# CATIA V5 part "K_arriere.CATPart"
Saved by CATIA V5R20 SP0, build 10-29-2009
Part number: arriere
Bounding box of the stored display mesh (mm): x -100 to 100, y 75.582 to 866, z -5 to 72.258
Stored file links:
  G:\Khaled_CFAO_2011\SIL\SIL_GR2\ahabrial\ahabrial\Khaled\CAD_ThinkMOTION\K_arriere.CATPart
  G:\Données\Ecole\IFMA\2A\Thinkmotion2\Etape18\trotinette.CATProduct
  G:\Khaled_CFAO_2011\SIL\SIL_GR2\ahabrial\ahabrial\Khaled\CAD_ThinkMOTION\K_avant.CATPart
  G:\Khaled_CFAO_2011\SIL\SIL_GR2\ahabrial\ahabrial\Khaled\CAD_ThinkMOTION\K_skl_arriere.CATPart
  G:\Khaled_CFAO_2011\SIL\SIL_GR2\ahabrial\ahabrial\Khaled\CAD_ThinkMOTION\K_guidon.CATPart
  G:\Khaled_CFAO_2011\SIL\SIL_GR2\ahabrial\ahabrial\Khaled\CAD_ThinkMOTION\K_skl_frein.CATPart
  G:\Khaled_CFAO_2011\SIL\SIL_GR2\ahabrial\ahabrial\Khaled\CAD_ThinkMOTION\K_bati.CATPart
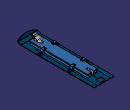
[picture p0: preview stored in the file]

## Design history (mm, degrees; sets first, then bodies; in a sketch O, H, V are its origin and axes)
Parameters
  `Longueur-arriere` = 740 mm
  Largeur_bande = 5 mm
  Profondeur_bande = 2 mm
  Longueur_arriere_trotinette = 590 mm
  Largeur_arriere_trotinette = 100 mm
  espace_frein = 50 mm
  epaisseur_arriere_trotinette = 30 mm
  `Diametre_trou_arriere trotinette` = 20 mm
  `epaisseur_supérieur_plateau_arriere_trotinette` = 10 mm
  Largeur_accroche_arriere = 25 mm
  Epaisseur_accroche_arriere = 10 mm
  Diametre_vis_accroche = 10 mm
  `Longueur_frein ` = 20 mm
External parameters (linked from other documents)
  External.epaisseur_planche_avant = 5 mm
  External.Largeur_planche_avant = 200 mm
  External.Longueur_arriere = 500 mm
  External.Hauteur_epaisseur_bati = 20 mm
  External.Largeur_epaisseur_bati = 10 mm
Set1
  Plane1 "Plan_avant_guidon": linked copy from another document
  Point1: linked copy from another document
  Line1 "Droite_arriere": linked copy from another document
  Line2 "Axe_frein_arriere": linked copy from another document
  Point2 "Point.4_frein": linked copy from another document
  Line3: linked copy from another document
  Line4 "Droite_frein": linked copy from another document
  Point3 "Point.3_arriere": linked copy from another document
  Plane2 "Plan_bati2": linked copy from another document
  Point4 "Point_construction": linked copy from another document
Body1 (main body)
  Sketch1 on Plane1, origin (0, 0, 0), H (1, 0, 0), V (0, -1, 0)
    line L1 (-100, -126) -> (100, -126)
    line L2 (100, -126) -> (100, -866)
    line L3 (100, -866) -> (-100, -866)
    line L4 (-100, -866) -> (-100, -126)
    reference projected point E1 (0, -200) from Point1
    reference projected point E2 (0, -200) from Point1
    length L4 = 740 {= `Longueur-arriere`}
    distance L1 E1 = 74 {= `Longueur-arriere` /10}
    distance E2 L4 = 100 {= External.Largeur_planche_avant /2}
    length L1 = 200 {= External.Largeur_planche_avant}
    horizontal: L1 H, L3 H
    vertical: L2 V, L4 V
  Pad1: profile Sketch1, direction (0, 0, -1), length 5 {= External.epaisseur_planche_avant}
  Sketch2 on end face of Pad1, origin (0, 0, -5), H (1, 0, 0), V (0, -1, 0)
    line L1 (-2.5, -220) -> (2.5, -220)
    line L2 (2.5, -220) -> (2.5, -890)
    line L3 (2.5, -890) -> (-2.5, -890)
    line L4 (-2.5, -890) -> (-2.5, -220)
    point P5 (64.1667, -220)
    line L5 (64.1667, -220) -> (69.1667, -220)
    line L6 (69.1667, -220) -> (69.1667, -890)
    line L7 (69.1667, -890) -> (64.1667, -890)
    line L8 (64.1667, -890) -> (64.1667, -220)
    point P6 (69.1667, -220)
    point P7 (69.1667, -890)
    point P8 (64.1667, -890)
    reference projected line E1 (0, -200) -> (0, -700) from Line1
    axis line L9 (66.6667, -313.0308) -> (66.6667, -613.0308)
    reference projected line E2 (0, -200) -> (0, -700) from Line1
    reference projected line E3 (0, -200) -> (0, -700) from edge of Line1
    point P13 (-64.1667, -220)
    point P14 (-64.1667, -890)
    line L10 (-64.1667, -890) -> (-64.1667, -220)
    reference projected line E4 (0, -200) -> (0, -700) from edge of Line1
    point P17 (-69.1667, -890)
    point P18 (-69.1667, -220)
    line L11 (-69.1667, -220) -> (-69.1667, -890)
    reference projected line E5 (0, -200) -> (0, -700) from edge of Line1
    point P21 (-69.1667, -220)
    point P22 (-64.1667, -220)
    line L12 (-64.1667, -220) -> (-69.1667, -220)
    reference projected line E6 (0, -200) -> (0, -700) from edge of Line1
    point P25 (-64.1667, -890)
    point P26 (-69.1667, -890)
    line L13 (-69.1667, -890) -> (-64.1667, -890)
    length L3 = 5 {= Largeur_bande}
    length L7 = 5 {= Largeur_bande}
    distance E1 L4 = 2.5 {= Largeur_bande /2}
    distance L9 E2 = 66.6667 {= External.Largeur_planche_avant /3}
    distance L9 L8 = 2.5 {= Largeur_bande /2}
    horizontal: L1 H, L3 H, L5 H, L7 H
    vertical: L2 V, L4 V, L6 V, L8 V, L9 V
    coincidence: P5 L1, P7 L3
    symmetry: P5 P13 E3, P8 P14 E3, L8 L10 E3, P7 P17 E4, P6 P18 E4, L6 L11 E4, P6 P21 E5, P5 P22 E5, L5 L12 E5, P8 P25 E6, P7 P26 E6, L7 L13 E6
  Pocket1: profile Sketch2, direction (0, 0, 1), length 2 {= Profondeur_bande}
  Plane3 "Plan_arriere_haut": type 2Lines, Element1 Line1, Element2 Line2
  Sketch3 on Plane3, origin (0, 0, 0), H (1, 0, 0), V (0, -1, 0)
    line L1 (-50, -160) -> (50, -160)
    line L2 (50, -160) -> (50, -750)
    line L3 (50, -750) -> (-50, -750)
    line L4 (-50, -750) -> (-50, -160)
    reference projected line E1 (0, -200) -> (0, -700) from Line1
    reference projected point E2 (0, -700) from Point2
    reference projected point E3 (0, -200) from Point3
    length L1 = 100 {= Largeur_arriere_trotinette}
    distance E1 L4 = 50 {= Largeur_arriere_trotinette /2}
    distance E2 L3 = 50 {= espace_frein}
    distance L1 E3 = 40 {= Longueur_arriere_trotinette -espace_frein -External.Longueur_arriere}
    horizontal: L1 H, L3 H
    vertical: L2 V, L4 V
  Pad2: profile Sketch3, direction (0, 0, 1), length 30 {= epaisseur_arriere_trotinette}
  Sketch4 on face of Pad2 from Sketch3.L3, origin (0, 750, 0), H (-1, 0, 0), V (0, 0, 1)
    circle A1 centre (-25, 15) radius 10
    point P1 (-25, 15)
    reference projected line E1 (0, 350) -> (0, 0) from Line3
    reference projected line E2 (20, 0) -> (-20, 0) from Line2
    circle A2 centre (25, 15) radius 10
    radius A1 = 10 {= `Diametre_trou_arriere trotinette` /2}
    distance E1 P1 = 25 {= Largeur_arriere_trotinette  /4}
    distance P1 E2 = 15 {= epaisseur_arriere_trotinette /2}
    symmetry: A1 A2 V
  Pocket2: profile Sketch4, direction (0, 1, 0), through (limit type 6)
  Sketch5 on face of Pad2 from Sketch3.L3, origin (0, 750, 0), H (-1, 0, 0), V (0, 0, 1)
    point P1 (25, 14.9997)
    reference projected line E1 (0, 350) -> (0, 0) from Line3
    reference projected line E2 (100, -0.0003) -> (-100, -0.0003) from edge [face of Pad1 | face of Pad1]
    line L1 (50, 19.9997) -> (37.3603, 19.9997)
    point P2 (50, 19.9997)
    point P3 (37.3603, 19.9997)
    line L2 (30, 0) -> (30, 2.6394)
    point P4 (30, 0)
    point P5 (30, 2.6394)
    reference projected line E3 (50, 0) -> (50, 30) from edge [face of Pad2 from Sketch3.L4 | face of Pad2 from Sketch3.L3]
    line L3 (50, 19.9997) -> (50, 0)
    point P6 (50, 0)
    line L4 (30, 0) -> (50, 0)
    arc A1 centre (25, 14.9997) radius 13.3333 from (30, 2.6394) to (37.3603, 19.9997) ccw
    point P7 (-37.3603, 19.9997)
    point P8 (-50, 19.9997)
    line L5 (-50, 19.9997) -> (-37.3603, 19.9997)
    point P9 (-37.3603, 19.9997)
    point P10 (-30, 2.6394)
    arc A2 centre (-25, 14.9997) radius 13.3333 from (-30, 2.6394) to (-37.3603, 19.9997) cw
    point P12 (-30, 2.6394)
    point P13 (-30, 0)
    line L6 (-30, 0) -> (-30, 2.6394)
    point P14 (-50, 0)
    point P15 (-30, 0)
    line L7 (-30, 0) -> (-50, 0)
    point P16 (-50, 0)
    point P17 (-50, 19.9997)
    line L8 (-50, 19.9997) -> (-50, 0)
    axis line L9 (30, 29.9997) -> (60, 29.9997)
    reference projected line E4 (100, -0.0003) -> (-100, -0.0003) from edge [face of Pad1 | face of Pad1]
    reference projected line E5 (20, 0) -> (-20, 0) from Line2
    distance P1 E1 = 25 {= Largeur_arriere_trotinette /4}
    distance P1 E2 = 15 {= epaisseur_arriere_trotinette /2}
    distance L9 E4 = 30 {= epaisseur_arriere_trotinette}
    distance L9 L1 = 10 {= `epaisseur_supérieur_plateau_arriere_trotinette`}
    horizontal: L1 H, L4 H, L9 H
    coincidence: P4 H, P2 E3, P6 H, P7 P9, P8 P17, P10 P12, P13 P15, P14 P16, L4 E5
    perpendicularity: L2 L1
    vertical: L3 V, L2 V
    symmetry: P3 P7 V, P2 P8 V, L1 L5 V, P3 P9 V, P5 P10 V, A1 A2 V, P5 P12 V, P4 P13 V, L2 L6 V, P6 P14 V, P4 P15 V, L4 L7 V, P6 P16 V, P2 P17 V, L3 L8 V
  Pocket3: profile Sketch5, direction (0, -1, 0), through (limit type 6)
  Sketch6 on face of Pad2 from Sketch3.L3, origin (0, 750, 0), H (-1, 0, 0), V (0, 0, 1)
    line L1 (-10, 20) -> (10, 20)
    line L2 (10, 20) -> (10, 0)
    line L3 (10, 0) -> (-10, 0)
    line L4 (-10, 0) -> (-10, 20)
    reference projected line E1 (20, 0) -> (-20, 0) from Line2
    reference projected line E2 (0, 350) -> (0, 0) from Line3
    reference projected line E3 (50, 30) -> (-50, 30) from edge [end face of Pad2 | face of Pad2 from Sketch3.L3]
    length L1 = 20 {= Largeur_arriere_trotinette /5}
    distance E2 L2 = 10 {= (Largeur_arriere_trotinette /5)/2}
    distance E3 L1 = 10 {= `epaisseur_supérieur_plateau_arriere_trotinette`}
    horizontal: L1 H, L3 H
    vertical: L2 V, L4 V
    coincidence: L3 E1
  Pocket4: profile Sketch6, direction (0, -1, 0), through (limit type 6)
  Sketch7 on Plane3, origin (0, 0, 0), H (1, 0, 0), V (0, -1, 0)
    point P1 (57.1429, -590)
    line L1 (57.1429, -590) -> (69.6429, -590)
    line L2 (69.6429, -590) -> (69.6429, -615)
    line L3 (69.6429, -615) -> (57.1429, -615)
    line L4 (57.1429, -615) -> (57.1429, -590)
    point P2 (69.6429, -590)
    point P3 (69.6429, -615)
    point P4 (57.1429, -615)
    construction line L5 (0, -602.5) -> (120, -602.5)
    reference projected line E1 (-50, -750) -> (50, -750) from edge [end face of Pad2 | face of Pad2 from Sketch3.L3]
    reference projected line E2 (0, -200) -> (0, -700) from edge of Line1
    point P9 (-57.1429, -590)
    point P10 (-57.1429, -615)
    line L6 (-57.1429, -615) -> (-57.1429, -590)
    point P11 (-69.6429, -590)
    line L7 (-57.1429, -590) -> (-69.6429, -590)
    point P12 (-69.6429, -615)
    line L8 (-69.6429, -590) -> (-69.6429, -615)
    line L9 (-69.6429, -615) -> (-57.1429, -615)
    axis line L10 (-150, -455) -> (220, -455)
    reference projected line E3 (-50, -750) -> (50, -750) from edge [end face of Pad2 | face of Pad2 from Sketch3.L3]
    point P15 (-69.6429, -295)
    point P16 (-69.6429, -320)
    line L11 (-69.6429, -320) -> (-69.6429, -295)
    point P17 (-57.1429, -320)
    line L12 (-57.1429, -320) -> (-69.6429, -320)
    point P18 (-57.1429, -295)
    line L13 (-57.1429, -295) -> (-57.1429, -320)
    line L14 (-69.6429, -295) -> (-57.1429, -295)
    point P19 (57.1429, -320)
    point P20 (57.1429, -295)
    line L15 (57.1429, -295) -> (57.1429, -320)
    point P21 (69.6429, -320)
    line L16 (57.1429, -320) -> (69.6429, -320)
    point P22 (69.6429, -295)
    line L17 (69.6429, -320) -> (69.6429, -295)
    line L18 (69.6429, -295) -> (57.1429, -295)
    reference projected line E4 (0, -200) -> (0, -700) from Line1
    length L1 = 12.5 {= Largeur_accroche_arriere /2}
    length L4 = 25 {= Largeur_accroche_arriere}
    distance L5 L1 = 12.5 {= Largeur_accroche_arriere /2}
    distance L5 E1 = 147.5 {= Longueur_arriere_trotinette /4}
    distance E3 L10 = 295 {= Longueur_arriere_trotinette /2}
    distance L4 E4 = 57.1429 {= Largeur_arriere_trotinette /1.75}
    horizontal: L1 H, L3 H, L5 H, L10 H
    vertical: L2 V, L4 V
    symmetry: P1 P9 E2, P4 P10 E2, L4 L6 E2, P2 P11 E2, L1 L7 E2, P3 P12 E2, L2 L8 E2, L3 L9 E2, P12 P15 L10, P11 P16 L10, L8 L11 L10, P9 P17 L10, L7 L12 L10, P10 P18 L10, L6 L13 L10, L9 L14 L10, P1 P19 L10, P4 P20 L10, L4 L15 L10, P2 P21 L10, L1 L16 L10, P3 P22 L10, L2 L17 L10, L3 L18 L10
  Pad3: profile Sketch7, direction (0, 0, 1), length 40 {= epaisseur_arriere_trotinette +Epaisseur_accroche_arriere}
  Sketch8 on face of Pad3 from Sketch7.L3, origin (0, 615, 0), H (-1, 0, 0), V (0, 0, 1)
    point P1 (-69.6429, 40)
    line L1 (-69.6429, 40) -> (-36.3095, 40)
    line L2 (-36.3095, 40) -> (-36.3095, 32.5)
    line L3 (-36.3095, 32.5) -> (-69.6429, 32.5)
    line L4 (-69.6429, 32.5) -> (-69.6429, 40)
    point P2 (-36.3095, 40)
    point P3 (-36.3095, 32.5)
    point P4 (-69.6429, 32.5)
    reference projected line E1 (-50, 40) -> (-75, 40) from edge [end face of Pad3 | face of Pad3 from Sketch7.L3]
    reference projected line E2 (-69.6429, 0) -> (-69.6429, 40) from edge [face of Pad3 from Sketch7.L3 | face of Pad3 from Sketch7.L2]
    point P5 (36.3095, 40)
    point P6 (69.6429, 40)
    line L5 (69.6429, 40) -> (36.3095, 40)
    point P7 (69.6429, 32.5)
    line L6 (69.6429, 32.5) -> (69.6429, 40)
    point P8 (36.3095, 32.5)
    line L7 (36.3095, 32.5) -> (69.6429, 32.5)
    line L8 (36.3095, 40) -> (36.3095, 32.5)
    distance L1 L3 = 7.5 {= Epaisseur_accroche_arriere /(4/3)}
    distance L4 L2 = 33.3333 {= Largeur_accroche_arriere *(4/3)}
    horizontal: L1 H, L3 H
    vertical: L2 V, L4 V
    coincidence: L1 E1, L4 E2
    symmetry: P2 P5 V, P1 P6 V, L1 L5 V, P4 P7 V, L4 L6 V, P3 P8 V, L3 L7 V, L2 L8 V
  Pad4: profile Sketch8, direction (0, -1, 0), length 25 {= Largeur_accroche_arriere}
  Sketch9 on face of Pad3 from Sketch7.L16, origin (0, 320, 0), H (-1, 0, 0), V (0, 0, 1)
    point P1 (-69.6429, 40)
    line L1 (-69.6429, 40) -> (-36.3095, 40)
    line L2 (-36.3095, 40) -> (-36.3095, 32.5)
    line L3 (-36.3095, 32.5) -> (-69.6429, 32.5)
    line L4 (-69.6429, 32.5) -> (-69.6429, 40)
    point P2 (-36.3095, 40)
    point P3 (-36.3095, 32.5)
    point P4 (-69.6429, 32.5)
    reference projected line E1 (-69.6429, 0) -> (-69.6429, 40) from edge [face of Pad3 from Sketch7.L16 | face of Pad3 from Sketch7.L17]
    reference projected line E2 (-57.1429, 40) -> (-82.1429, 40) from edge [end face of Pad3 | face of Pad3 from Sketch7.L16]
    point P5 (36.3095, 40)
    point P6 (69.6429, 40)
    line L5 (69.6429, 40) -> (36.3095, 40)
    point P7 (69.6429, 32.5)
    line L6 (69.6429, 32.5) -> (69.6429, 40)
    point P8 (36.3095, 32.5)
    line L7 (36.3095, 32.5) -> (69.6429, 32.5)
    line L8 (36.3095, 40) -> (36.3095, 32.5)
    distance L4 L2 = 33.3333 {= Largeur_accroche_arriere *(4/3)}
    distance L1 L3 = 7.5 {= Epaisseur_accroche_arriere /(4/3)}
    horizontal: L1 H, L3 H
    vertical: L2 V, L4 V
    coincidence: L4 E1, L1 E2
    symmetry: P2 P5 V, P1 P6 V, L1 L5 V, P4 P7 V, L4 L6 V, P3 P8 V, L3 L7 V, L2 L8 V
  Pad5: profile Sketch9, direction (0, -1, 0), length 25 {= Largeur_accroche_arriere}
  Sketch10 on face of Pad5, origin (0, 0, 40), H (1, 0, 0), V (0, 1, 0)
    circle A1 centre (44.6429, 307.5) radius 5
    point P1 (44.6429, 307.5)
    reference projected line E1 (57.1429, 320) -> (82.1429, 320) from edge [face of Pad5 | face of Pad5]
    reference projected line E2 (36.3095, 340) -> (36.3095, 290) from edge [face of Pad5 from Sketch9.L2 | face of Pad5 from Sketch9.L1]
    reference projected line E3 (0, 200) -> (0, 700) from edge of Line1
    circle A2 centre (-44.6429, 307.5) radius 5
    axis line L1 (-130, 455) -> (130, 455)
    reference projected line E4 (50, 160) -> (-50, 160) from edge [end face of Pad2 | face of Pad2 from Sketch3.L1]
    circle A3 centre (44.6429, 602.5) radius 5
    circle A4 centre (-44.6429, 602.5) radius 5
    radius A1 = 5 {= Diametre_vis_accroche /2}
    distance P1 E1 = 12.5 {= Largeur_accroche_arriere /2}
    distance P1 E2 = 8.3333 {= Largeur_accroche_arriere /3}
    distance L1 E4 = 295 {= Longueur_arriere_trotinette /2}
    symmetry: A1 A2 E3, A1 A3 L1, A2 A4 L1
    horizontal: L1 H
  Pocket5: profile Sketch10, direction (0, 0, -1), through (limit type 6)
  Sketch11 on end face of Pad2, origin (0, 0, 30), H (1, 0, 0), V (0, 1, 0)
    line L1 (-10, 750) -> (10, 750)
    line L2 (10, 750) -> (10, 690)
    line L3 (10, 690) -> (-10, 690)
    line L4 (-10, 690) -> (-10, 750)
    reference projected line E1 (-50, 750) -> (50, 750) from edge [end face of Pad2 | face of Pad2 from Sketch3.L3]
    reference projected line E2 (0, 700) -> (0, 770.7107) from Line4
    distance L1 L3 = 60
    distance L4 L2 = 20 {= Largeur_arriere_trotinette /5}
    distance L4 E2 = 10 {= (Largeur_arriere_trotinette /5)/2}
    horizontal: L1 H, L3 H
    vertical: L2 V, L4 V
    coincidence: L1 E1
  Pocket6: profile Sketch11, direction (0, 0, -1), length 30 {= epaisseur_arriere_trotinette}
  Sketch12 on face of Pad1, origin (0, 0, 0), H (1, 0, 0), V (0, 1, 0)
    line L1 (-25, 853.5) -> (25, 853.5)
    line L2 (25, 853.5) -> (25, 803.5)
    line L3 (25, 803.5) -> (-25, 803.5)
    line L4 (-25, 803.5) -> (-25, 853.5)
    reference projected line E1 (0, 200) -> (0, 700) from Line1
    reference projected line E2 (-100, 866) -> (100, 866) from edge [face of Pad1 | face of Pad1]
    length L1 = 50 {= espace_frein}
    distance L4 E1 = 25 {= espace_frein /2}
    distance L1 L3 = 50 {= espace_frein}
    distance E2 L1 = 12.5 {= espace_frein /4}
    horizontal: L1 H, L3 H
    vertical: L2 V, L4 V
  Pocket7: profile Sketch12, direction (0, 0, -1), through (limit type 6)
  Plane4 "Plan_constuction_avant_arrondi": type Angle, RefPlane face of Pad1 from Sketch1.L1, Direction edge [face of Pad1 from Sketch1.L1 | end face of Pad1], Angle -65
  Sketch13 on Plane4, origin (0, 42.0478, 34.1475), H (-1, 0, 0), V (0, -0.9063, 0.4226)
    line L1 (-100, -55.631) -> (100, -55.631)
    line L2 (100, -55.631) -> (100, -92.631)
    line L3 (100, -92.631) -> (-100, -92.631)
    line L4 (-100, -92.631) -> (-100, -55.631)
    point P4 (-100, -92.631)
    reference projected line E1 (-100, -92.631) -> (100, -92.631) from edge [face of Pad1 from Sketch1.L1 | end face of Pad1]
    reference projected point E2 (-100, -92.631) from vertex [face of Pad1 from Sketch1.L1 | end face of Pad1 | face of Pad1 from Sketch1.L2]
    length L3 = 200 {= External.Largeur_planche_avant}
    length L4 = 37 {= `Longueur-arriere` /20}
    horizontal: L1 H, L3 H
    vertical: L2 V, L4 V
    coincidence: L3 E1, E2 P4
  Pad6: profile Sketch13, direction (0, 0.4226, 0.9063), length 5 {= External.epaisseur_planche_avant}
  Fillet1: radius 5, on edge [end face of Pad6 | start face of Pad1]
  Plane5 "Plan_construction_avnt_arrondi2": type Angle, RefPlane face of Pad6 from Sketch13.L1, Direction edge [start face of Pad6 | face of Pad6 from Sketch13.L1], Angle -120
  Sketch14 on Plane5, origin (0, 75.5818, 34.7509), H (1, 0, 0), V (0, -0.5736, 0.8192)
    line L1 (0, -29.4378) -> (100, -29.4378)
    point P1 (0, -29.4378)
    point P2 (100, -29.4378)
    reference projected line E1 (-100, -29.4378) -> (100, -29.4378) from edge [start face of Pad6 | face of Pad6 from Sketch13.L1]
    reference projected point E2 (100, -29.4378) from vertex [face of Pad6 from Sketch13.L4 | start face of Pad6 | face of Pad6 from Sketch13.L1]
    axis line L2 (0, 0) -> (0, -70)
    spline S1 through (100, -29.4378) (88.9437, -21.8125) (29.6977, -2.0626) (0, 0)
    spline S2 through (-100, -29.4378) (-88.9437, -21.8125) (-29.6977, -2.0626) (0, 0)
    point P4 (-100, -29.4378)
    point P5 (0, -29.4378)
    line L3 (0, -29.4378) -> (-100, -29.4378)
    point P6 (100, -29.4378)
    point P7 (0, 0)
    point P8 (0, 0)
    point P9 (-100, -29.4378)
    point P10 (29.6977, -2.0626)
    point P11 (-29.6977, -2.0626)
    point P12 (88.9437, -21.8125)
    point P13 (-88.9437, -21.8125)
    length L1 = 100 {= External.Largeur_planche_avant /2}
    horizontal: L1 H
    coincidence: L1 E1, P2 E2, P6 P2, P7 O
    vertical: L2 V
    symmetry: S1 S2 L2, P2 P4 L2, P1 P5 L2, L1 L3 L2, P7 P8 L2, P6 P9 L2, P10 P11 L2, P12 P13 L2
    tangency: S2 S1
  Pad7: profile Sketch14, direction (0, 0.8192, 0.5736), length 5 {= External.epaisseur_planche_avant}
  Fillet2: radius 5, on edge [end face of Pad6 | end face of Pad7]
  Fillet3: radius 5, on edge [start face of Pad6 | end face of Pad1]; edge [start face of Pad6 | start face of Pad7]
  Sketch15 on Plane2, origin (0, 101.3062, -86.1103), H (-1, 0, 0), V (0, 0.6476, 0.7619)
    construction line L1 (0, 142.3879) -> (0, 162.3879)
    point P2 (0, 162.3879)
    line L2 (-20, 142.3879) -> (-20, 162.3879)
    line L3 (20, 162.3879) -> (20, 142.3879)
    arc A1 centre (0, 162.3879) radius 20 from (-20, 162.3879) to (20, 162.3879) cw
    arc A2 centre (0, 142.3879) radius 20 from (20, 142.3879) to (-20, 142.3879) cw
    reference projected point E1 (0, 152.3879) from Point4
    reference projected point E2 (0, 152.3879) from Point4
    construction line L4 (0, 162.3879) -> (0, 142.3879)
    point P7 (0, 162.3879)
    line L5 (10, 162.3879) -> (10, 142.3879)
    line L6 (-10, 142.3879) -> (-10, 162.3879)
    arc A3 centre (0, 142.3879) radius 10 from (10, 142.3879) to (-10, 142.3879) cw
    arc A4 centre (0, 162.3879) radius 10 from (-10, 162.3879) to (10, 162.3879) cw
    reference projected point E3 (0, 152.3879) from Point4
    reference projected point E4 (0, 152.3879) from Point4
    distance L1 L2 = 20 {= External.Largeur_epaisseur_bati +10mm}
    length L1 = 20 {= External.Hauteur_epaisseur_bati}
    distance P2 E2 = 10 {= External.Hauteur_epaisseur_bati /2}
    distance L4 L5 = 10 {= External.Largeur_epaisseur_bati}
    length L4 = 20 {= External.Hauteur_epaisseur_bati}
    distance P7 E4 = 10 {= External.Hauteur_epaisseur_bati /2}
    vertical: L1 V, L4 V
    tangency: A1 L2, A2 L2, A1 L3, A2 L3, A3 L5, A4 L5, A3 L6, A4 L6
    coincidence: L1 E1, L4 E3
  Pad8: profile Sketch15, direction (0, -0.7619, 0.6476), length 30 {= epaisseur_arriere_trotinette}
  Sketch16 on Plane2, origin (0, 101.3062, -86.1103), H (-1, 0, 0), V (0, 0.6476, 0.7619)
    line L1 (0, 152.3879) -> (20, 152.3879)
    point P1 (0, 152.3879)
    point P2 (20, 152.3879)
    line L2 (20, 152.3879) -> (20, 162.3879)
    point P3 (20, 162.3879)
    arc A1 centre (0, 162.3879) radius 20 from (20, 162.3879) to (0, 182.3879) ccw
    point P4 (0, 162.3879)
    point P5 (0, 182.3879)
    axis line L3 (0, 180) -> (0, 140)
    reference projected point E1 (0, 152.3879) from Point4
    reference projected point E2 (0, 152.3879) from Point4
    point P8 (0, 182.3879)
    point P9 (-20, 162.3879)
    arc A2 centre (0, 162.3879) radius 20 from (-20, 162.3879) to (0, 182.3879) cw
    point P11 (-20, 152.3879)
    line L4 (-20, 152.3879) -> (-20, 162.3879)
    point P12 (0, 152.3879)
    line L5 (0, 152.3879) -> (-20, 152.3879)
    radius A1 = 20 {= External.Largeur_epaisseur_bati +10mm}
    length L2 = 10 {= External.Hauteur_epaisseur_bati /2}
    length L1 = 20 {= External.Largeur_epaisseur_bati +10mm}
    distance P4 E2 = 10 {= External.Hauteur_epaisseur_bati /2}
    horizontal: L1 H
    vertical: L2 V, L3 V
    tangency: A1 L2
    coincidence: P1 L3, P5 L3, E1 L3, P1 P12, P5 P8
    symmetry: P5 P8 L3, P3 P9 L3, A1 A2 L3, P2 P11 L3, L2 L4 L3, P1 P12 L3, L1 L5 L3
  Pad9: profile Sketch16, direction (0, 0.7619, -0.6476), length 45 {= epaisseur_arriere_trotinette *1.5}
  Sketch17 on face of Pad9, origin (20, 0, 0), H (0, 1, 0), V (0, 0, 1)
    line L1 (170.6653, 41.8101) -> (158.922, 51.7919)
    point P1 (170.6653, 41.8101)
    point P2 (158.922, 51.7919)
    line L2 (183.6183, 57.0488) -> (171.875, 67.0307)
    point P3 (183.6183, 57.0488)
    arc A1 centre (165.3985, 59.4113) radius 10 from (171.875, 67.0307) to (158.922, 51.7919) ccw
    point P5 (165.3985, 59.4113)
    reference projected line E1 (184.5595, 30) -> (170.6653, 41.8101) from edge [face of Pad9 | face of Pad8 from Sketch15.A2]
    reference projected line E3 (183.6183, 57.0488) -> (170.6653, 41.8101) from edge [end face of Pad8 | face of Pad8 from Sketch15.L2]
    reference projected point E4 (183.6183, 57.0488) from vertex [face of Pad8 from Sketch15.L2 | end face of Pad8 | face of Pad8 from Sketch15.A1]
    line L3 (183.6183, 57.0488) -> (170.6653, 41.8101)
    distance L2 L1 = 20
    distance P5 P2 = 10
    tangency: A1 L1
    parallelism: L1 E1
    coincidence: P1 E3, P3 E4
    perpendicularity: L3 L1
  Pad10: profile Sketch17, direction (-1, 0, 0), length 40 {= (External.Largeur_epaisseur_bati +10mm)*2}
  Sketch18 on face of Pad10, origin (20, 0, 0), H (0, 1, 0), V (0, 0, 1)
    construction line L1 (165.3985, 59.4113) -> (180.6373, 46.4583)
    point P1 (165.3985, 59.4113)
    line L2 (168.6368, 63.221) -> (183.8755, 50.268)
    line L3 (177.3991, 42.6486) -> (162.1603, 55.6016)
    arc A1 centre (180.6373, 46.4583) radius 5 from (183.8755, 50.268) to (177.3991, 42.6486) cw
    arc A2 centre (165.3985, 59.4113) radius 5 from (162.1603, 55.6016) to (168.6368, 63.221) cw
    reference projected line E1 (206.4765, 37.6194) -> (183.6183, 57.0488) from edge [face of Pad9 | face of Pad10]
    reference projected line E2 (206.4765, 37.6194) -> (183.6183, 57.0488) from edge [face of Pad9 | face of Pad10]
    reference projected arc E3 centre (165.3985, 59.4113) radius 10 from (171.875, 67.0307) to (158.922, 51.7919) ccw from edge [face of Pad10 from Sketch17.A1 | start face of Pad10]
    distance L1 L2 = 5 {= External.Largeur_epaisseur_bati /2}
    distance E2 L1 = 10 {= External.Largeur_epaisseur_bati}
    distance E3 P1 = 10 {= External.Largeur_epaisseur_bati}
    length L1 = 20 {= External.Hauteur_epaisseur_bati}
    tangency: A1 L2, A2 L2, A1 L3, A2 L3
    parallelism: L1 E1
  Pocket8: profile Sketch18, direction (-1, 0, 0), through (limit type 3)
  Fillet4: radius 5, on edge [end face of Pad8 | face of Pad10 from Sketch17.L2] (x2); edge [face of Pad10 from Sketch17.L1 | end face of Pad8] (x2)
  Sketch19 on start face of Pad1, origin (0, 0, 0), H (1, 0, 0), V (0, 1, 0)
    point P1 (69.6429, 615)
    line L1 (69.6429, 615) -> (94.6429, 615)
    line L2 (94.6429, 615) -> (94.6429, 590)
    line L3 (94.6429, 590) -> (69.6429, 590)
    line L4 (69.6429, 590) -> (69.6429, 615)
    point P2 (94.6429, 615)
    point P3 (94.6429, 590)
    point P4 (69.6429, 590)
    reference projected line E1 (69.6429, 615) -> (69.6429, 590) from edge [face of Pad4 | face of Pad4]
    reference projected point E2 (69.6429, 590) from vertex [face of Pad4 | face of Pad4 | face of Pad4]
    reference projected point E3 (69.6429, 615) from vertex [face of Pad4 | face of Pad4 | face of Pad4]
    construction line L5 (0, 650) -> (0, 570)
    reference projected line E4 (0, 200) -> (0, 700) from Line1
    point P7 (-94.6429, 615)
    point P8 (-69.6429, 615)
    line L6 (-69.6429, 615) -> (-94.6429, 615)
    point P9 (-69.6429, 590)
    line L7 (-69.6429, 590) -> (-69.6429, 615)
    point P10 (-94.6429, 590)
    line L8 (-94.6429, 590) -> (-69.6429, 590)
    line L9 (-94.6429, 615) -> (-94.6429, 590)
    axis line L10 (-150, 455) -> (240, 455)
    point P13 (94.6429, 295)
    point P14 (69.6429, 295)
    line L11 (69.6429, 295) -> (94.6429, 295)
    point P15 (69.6429, 320)
    line L12 (69.6429, 320) -> (69.6429, 295)
    point P16 (94.6429, 320)
    line L13 (94.6429, 320) -> (69.6429, 320)
    line L14 (94.6429, 295) -> (94.6429, 320)
    point P17 (-94.6429, 295)
    point P18 (-69.6429, 295)
    line L15 (-69.6429, 295) -> (-94.6429, 295)
    point P19 (-94.6429, 320)
    line L16 (-94.6429, 295) -> (-94.6429, 320)
    point P20 (-69.6429, 320)
    line L17 (-94.6429, 320) -> (-69.6429, 320)
    line L18 (-69.6429, 320) -> (-69.6429, 295)
    length L1 = 25 {= Largeur_accroche_arriere}
    distance L3 L10 = 135 {= 270mm/2}
    horizontal: L1 H, L3 H, L10 H
    vertical: L2 V, L4 V, L5 V
    coincidence: L4 E1, P4 E2, P1 E3, E4 L5
    symmetry: P2 P7 L5, P1 P8 L5, L1 L6 L5, P4 P9 L5, L4 L7 L5, P3 P10 L5, L3 L8 L5, L2 L9 L5, P2 P13 L10, P1 P14 L10, L1 L11 L10, P4 P15 L10, L4 L12 L10, P3 P16 L10, L3 L13 L10, L2 L14 L10, P7 P17 L10, P8 P18 L10, L6 L15 L10, P10 P19 L10, L9 L16 L10, P9 P20 L10, L8 L17 L10, L7 L18 L10
  Pad11: profile Sketch19, direction (0, 0, 1), length 10 {= Epaisseur_accroche_arriere}
  Sketch20 on end face of Pad11, origin (0, 0, 10), H (1, 0, 0), V (0, 1, 0)
    construction line L1 (75.8929, 602.5) -> (88.3929, 602.5)
    point P1 (75.8929, 602.5)
    line L2 (75.8929, 607.5) -> (88.3929, 607.5)
    line L3 (88.3929, 597.5) -> (75.8929, 597.5)
    arc A1 centre (88.3929, 602.5) radius 5 from (88.3929, 607.5) to (88.3929, 597.5) cw
    arc A2 centre (75.8929, 602.5) radius 5 from (75.8929, 597.5) to (75.8929, 607.5) cw
    point P3 (75.8929, 607.5)
    point P4 (88.3929, 607.5)
    point P5 (88.3929, 597.5)
    point P6 (75.8929, 597.5)
    reference projected line E1 (88.3929, 615) -> (69.6429, 615) from edge [face of Pad11 from Sketch19.L1 | end face of Pad11]
    reference projected line E2 (69.6429, 615) -> (69.6429, 590) from edge [face of Pad4 | face of Pad4]
    reference projected line E3 (0, 200) -> (0, 700) from edge of Line1
    point P9 (-88.3929, 607.5)
    point P10 (-75.8929, 607.5)
    line L4 (-75.8929, 607.5) -> (-88.3929, 607.5)
    point P11 (-75.8929, 597.5)
    arc A3 centre (-75.8929, 602.5) radius 5 from (-75.8929, 597.5) to (-75.8929, 607.5) ccw
    point P13 (-88.3929, 597.5)
    line L5 (-88.3929, 597.5) -> (-75.8929, 597.5)
    arc A4 centre (-88.3929, 602.5) radius 5 from (-88.3929, 607.5) to (-88.3929, 597.5) ccw
    axis line L6 (-170, 455) -> (190, 455)
    reference projected line E4 (57.1429, 590) -> (69.6429, 590) from edge [face of Pad4 | face of Pad4]
    point P17 (88.3929, 302.5)
    point P18 (75.8929, 302.5)
    line L7 (75.8929, 302.5) -> (88.3929, 302.5)
    point P19 (75.8929, 312.5)
    arc A5 centre (75.8929, 307.5) radius 5 from (75.8929, 312.5) to (75.8929, 302.5) ccw
    point P21 (88.3929, 312.5)
    line L8 (88.3929, 312.5) -> (75.8929, 312.5)
    arc A6 centre (88.3929, 307.5) radius 5 from (88.3929, 302.5) to (88.3929, 312.5) ccw
    point P23 (-88.3929, 302.5)
    point P24 (-75.8929, 302.5)
    line L9 (-75.8929, 302.5) -> (-88.3929, 302.5)
    point P25 (-88.3929, 312.5)
    arc A7 centre (-88.3929, 307.5) radius 5 from (-88.3929, 302.5) to (-88.3929, 312.5) cw
    point P27 (-75.8929, 312.5)
    line L10 (-88.3929, 312.5) -> (-75.8929, 312.5)
    arc A8 centre (-75.8929, 307.5) radius 5 from (-75.8929, 312.5) to (-75.8929, 302.5) cw
    distance L1 L2 = 5 {= Diametre_vis_accroche /2}
    distance L1 E1 = 12.5 {= Largeur_accroche_arriere /2}
    length L1 = 12.5 {= Largeur_accroche_arriere /2}
    distance P1 E2 = 6.25 {= Largeur_accroche_arriere /4}
    distance L6 E4 = 135 {= 270mm/2}
    horizontal: L1 H, L6 H
    tangency: A1 L2, A2 L2, A1 L3, A2 L3
    symmetry: P4 P9 E3, P3 P10 E3, L2 L4 E3, P6 P11 E3, A2 A3 E3, P5 P13 E3, L3 L5 E3, A1 A4 E3, P4 P17 L6, P3 P18 L6, L2 L7 L6, P6 P19 L6, A2 A5 L6, P5 P21 L6, L3 L8 L6, A1 A6 L6, P9 P23 L6, P10 P24 L6, L4 L9 L6, P13 P25 L6, A4 A7 L6, P11 P27 L6, L5 L10 L6, A3 A8 L6
  Pocket9: profile Sketch20, direction (0, 0, -1), length 10 {= Epaisseur_accroche_arriere}
  Sketch21 on start face of Pad1, origin (0, 0, 0), H (1, 0, 0), V (0, 1, 0)
    circle A1 centre (75.8929, 307.5) radius 5
    reference projected arc E1 centre (75.8929, 307.5) radius 5 from (75.8929, 312.5) to (75.8929, 302.5) ccw from edge [end face of Pad11 | face of Pocket9 from Sketch20.A5]
    circle A2 centre (-75.8929, 307.5) radius 5
    circle A3 centre (75.8929, 602.5) radius 5
    circle A4 centre (-75.8929, 602.5) radius 5
    reference projected arc E2 centre (-75.8929, 307.5) radius 5 from (-75.8929, 302.5) to (-75.8929, 312.5) ccw from edge [end face of Pad11 | face of Pocket9 from Sketch20.A8]
    reference projected arc E3 centre (-75.8929, 602.5) radius 5 from (-75.8929, 597.5) to (-75.8929, 607.5) ccw from edge [end face of Pad11 | face of Pocket9 from Sketch20.A3]
    reference projected arc E4 centre (75.8929, 602.5) radius 5 from (75.8929, 607.5) to (75.8929, 597.5) ccw from edge [end face of Pad11 | face of Pocket9 from Sketch20.A2]
    radius A1 = 5 {= Diametre_vis_accroche /2}
    concentricity: A1 E1, A2 E2, A4 E3, A3 E4
  Pocket10: profile Sketch21, direction (0, 0, -1), length 2.5 {= External.epaisseur_planche_avant /2}
  Sketch22 on end face of Pad11, origin (0, 0, 10), H (1, 0, 0), V (0, 1, 0)
    circle A1 centre (75.8929, 602.5) radius 5
    reference projected arc E1 centre (75.8929, 602.5) radius 5 from (75.8929, 597.5) to (75.8929, 607.5) ccw from edge [end face of Pocket9 | face of Pocket10]
    circle A2 centre (-75.8929, 602.5) radius 5
    circle A3 centre (75.8929, 307.5) radius 5
    circle A4 centre (-75.8929, 307.5) radius 5
    reference projected arc E2 centre (-75.8929, 602.5) radius 5 from (-75.8929, 607.5) to (-75.8929, 597.5) ccw from edge [end face of Pocket9 | face of Pocket10 from Sketch21.A4]
    reference projected arc E3 centre (75.8929, 307.5) radius 5 from (75.8929, 302.5) to (75.8929, 312.5) ccw from edge [end face of Pocket9 | face of Pocket10]
    reference projected arc E4 centre (-75.8929, 307.5) radius 5 from (-75.8929, 312.5) to (-75.8929, 302.5) ccw from edge [end face of Pocket9 | face of Pocket10 from Sketch21.A2]
    radius A1 = 5 {= Diametre_vis_accroche /2}
    concentricity: A1 E1, A2 E2, A3 E3, A4 E4
  Pad12: profile Sketch22, direction (0, 0, -1), length 12.5 {= (External.epaisseur_planche_avant /2)+Epaisseur_accroche_arriere}
  Sketch23 on face of Pad12, origin (0, 0, 10), H (1, 0, 0), V (0, 1, 0)
    circle A1 centre (75.8929, 602.5) radius 6
    circle A2 centre (-75.8929, 602.5) radius 6
    circle A3 centre (75.8929, 307.5) radius 6
    circle A4 centre (-75.8929, 307.5) radius 6
    reference projected circle E1 centre (-75.8929, 602.5) radius 5 from edge [face of Pad12 from Sketch22.A2 | face of Pad12]
    reference projected circle E2 centre (75.8929, 307.5) radius 5 from edge [face of Pad12 from Sketch22.A3 | face of Pad12]
    reference projected circle E3 centre (-75.8929, 307.5) radius 5 from edge [face of Pad12 from Sketch22.A4 | face of Pad12]
    reference projected circle E4 centre (75.8929, 602.5) radius 5 from edge [face of Pad12 from Sketch22.A1 | face of Pad12]
    radius A1 = 6 {= (Diametre_vis_accroche +2mm)/2}
    concentricity: A2 E1, A3 E2, A4 E3, A1 E4
  Pad13: profile Sketch23, direction (0, 0, 1), length 5
  Sketch24 on face of Pocket6, origin (10, 0, 0), H (0, -1, 0), V (0, 0, 1)
    circle A1 centre (-710.3732, 17.4388) radius 5.625
    radius A1 = 5.625
  Pad14: profile Sketch24, direction (-1, 0, 0), up to the existing solid (limit type 2)
Relations
  Pocket9.FirstLimit.Depth = Epaisseur_accroche_arriere (deactivated)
